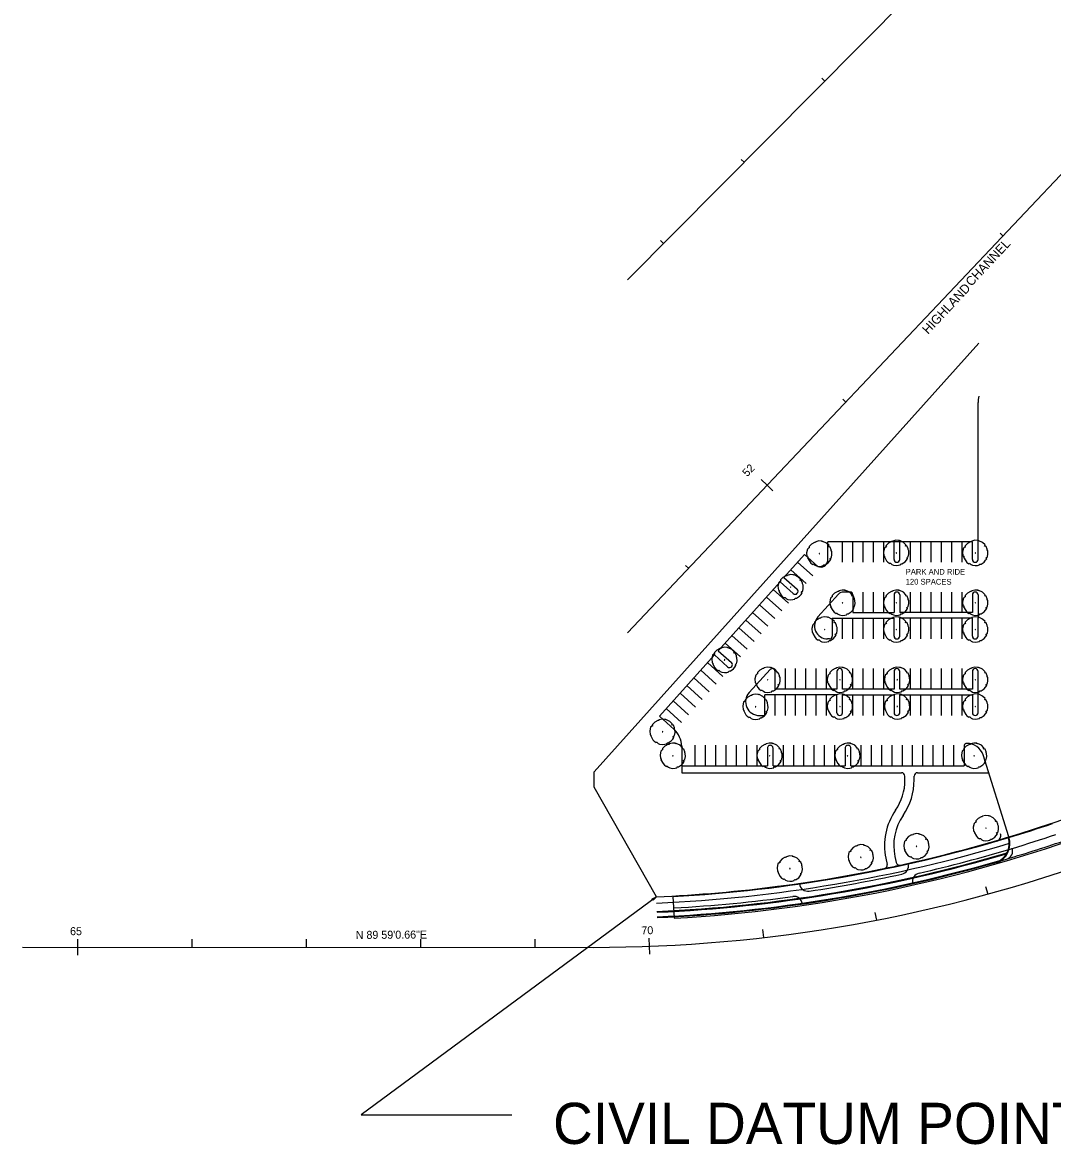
# Model space of a CAD drawing. Extents: x 6711323 to 6714641, y 1869258 to 1871224.
# Drawn here: x 6711323 to 6712223, y 1869258 to 1870239 of the extents above; entities that cross this region are included whole.
import ezdxf

# ---------------------------------------------------------------- set-up
doc = ezdxf.new("R2010")
doc.units = 0
for name, color, linetype in [('Level 10', 7, 'Continuous'), ('Level 11', 7, 'Continuous'), ('Level 13', 7, 'Continuous'), ('Level 14', 7, 'Continuous'), ('Level 15', 7, 'Continuous'), ('Level 16', 7, 'Continuous'), ('Level 18', 7, 'Continuous'), ('Level 2', 7, 'Continuous'), ('Level 3', 7, 'Continuous'), ('Level 32', 7, 'Continuous'), ('Level 35', 7, 'Continuous'), ('Level 46', 7, 'Continuous'), ('Level 63', 7, 'Continuous')]:
    doc.layers.add(name, color=color, linetype=linetype)

# ---------------------------------------------------------------- blocks, each defined once
blk = doc.blocks.new('TREE_1')
at = {"layer": 'Level 18'}
for p, q in [((-0.223, 0.51), (-0.357, 0.436)), ((-0.203, 0.506), (-0.223, 0.51)), ((-0.178, 0.51), (-0.203, 0.506)), ((-0.168, 0.532), (-0.178, 0.51)), ((-0.027, 0.572), (-0.168, 0.532)), ((0.117, 0.559), (-0.027, 0.572)), ((0.117, 0.537), (0.117, 0.559)), ((0.144, 0.55), (0.117, 0.537)), ((0.312, 0.471), (0.144, 0.55)), ((-0.539, 0.216), (-0.577, 0.053)), ((-0.577, 0.053), (-0.559, -0.123)), ((-0.491, 0.26), (-0.539, 0.216)), ((-0.46, 0.264), (-0.491, 0.26)), ((-0.46, 0.33), (-0.467, 0.29)), ((-0.467, 0.29), (-0.45, 0.286)), ((-0.357, 0.436), (-0.46, 0.33)), ((-0.45, 0.286), (-0.46, 0.264)), ((-0.003, 0.018), (-0.021, 0.009)), ((-0.021, 0.009), (-0.014, 0)), ((-0.014, 0), (0, 0)), ((0, 0), (-0.003, 0.018)), ((0.419, 0.365), (0.312, 0.471)), ((0.398, 0.317), (0.415, 0.334)), ((0.408, 0.308), (0.398, 0.317)), ((0.436, 0.317), (0.408, 0.308)), ((0.415, 0.334), (0.419, 0.365)), ((0.474, 0.295), (0.436, 0.317)), ((0.518, 0.185), (0.474, 0.295)), ((0.518, 0.15), (0.518, 0.185)), ((0.542, 0.101), (0.518, 0.15)), ((0.549, -0.031), (0.542, 0.101)), ((-0.559, -0.123), (-0.529, -0.136)), ((-0.525, -0.163), (-0.535, -0.176)), ((-0.535, -0.176), (-0.439, -0.343)), ((-0.529, -0.136), (-0.525, -0.163)), ((-0.439, -0.343), (-0.384, -0.414)), ((-0.384, -0.414), (-0.295, -0.466)), ((-0.295, -0.466), (-0.281, -0.458)), ((-0.281, -0.458), (-0.261, -0.449)), ((-0.261, -0.449), (-0.247, -0.466)), ((-0.247, -0.466), (-0.199, -0.506)), ((0.178, -0.506), (0.192, -0.488)), ((0.192, -0.488), (0.227, -0.484)), ((0.227, -0.484), (0.244, -0.488)), ((0.244, -0.488), (0.381, -0.396)), ((0.381, -0.396), (0.446, -0.317)), ((0.446, -0.317), (0.494, -0.246)), ((0.463, -0.207), (0.484, -0.189)), ((0.47, -0.229), (0.463, -0.207)), ((0.484, -0.229), (0.47, -0.229)), ((0.484, -0.189), (0.525, -0.163)), ((0.494, -0.246), (0.484, -0.229)), ((0.525, -0.163), (0.549, -0.031)), ((-0.199, -0.506), (-0.137, -0.537)), ((-0.137, -0.537), (-0.017, -0.554)), ((-0.017, -0.554), (0.089, -0.546)), ((0.089, -0.546), (0.175, -0.524)), ((0.175, -0.524), (0.178, -0.506))]:
    blk.add_line(p, q, dxfattribs=at)

msp = doc.modelspace()

# ---------------------------------------------------------------- linework, layer by layer
at = {"layer": 'Level 10'}
for radius, end in [(1262.51, 286.74398), (1269.84, 286.54272), (1270.51, 286.51109), (1274.53, 286.18152), (1275.2, 285.96183)]:
    msp.add_arc((6711821.84, 1870730.35), radius, 272.50226, end, dxfattribs=at)
at = {"layer": 'Level 11'}
for p, q in [((6712023.87, 1870187.68), (6712021.39, 1870190.15)), ((6711953.42, 1870116.72), (6711950.93, 1870119.19)), ((6711882.96, 1870045.76), (6711880.48, 1870048.22)), ((6711891.19, 1869474.76), (6711892.24, 1869455.79))]:
    msp.add_line(p, q, dxfattribs=at)
for centre, radius, start, end in [((6711821.85, 1870730.35), 1257.5, 286.77978, 288.60239), ((6711821.85, 1870730.35), 1257.5, 273.16115, 286.77978), ((6711821.85, 1870730.35), 1276.5, 273.16115, 290.14901), ((6712172.81, 1869528.03), 5, 286.27284, 17.69104), ((6711821.85, 1870730.35), 1267.5, 286.78697, 288.5952), ((6711821.85, 1870730.35), 1267.5, 282.97403, 286.78697), ((6711821.85, 1870730.35), 1275, 286.44789, 288.93429), ((6712180.73, 1869514.72), 7.5, 286.44789, 17.69109), ((6711821.85, 1870730.35), 1275, 273.16115, 286.44789), ((6712089.63, 1869501.69), 7.5, 282.29527, 12.63699), ((6712009.27, 1869486.89), 7.5, 188.22963, 278.57135), ((6711821.85, 1870730.35), 1265, 278.57135, 282.29527), ((6712108.1, 1869487.9), 7.5, 102.97403, 192.63699), ((6711821.85, 1870730.35), 1267.5, 273.16115, 277.89259), ((6711996.93, 1869467.43), 7.5, 8.22963, 97.89259)]:
    msp.add_arc(centre, radius, start, end, dxfattribs=at)
at = {"layer": 'Level 13'}
for p, q in [((6711851.4, 1869705.32), (6712288.61, 1870167.5)), ((6711322.58, 1869430.49), (6711821.47, 1869430.35))]:
    msp.add_line(p, q, dxfattribs=at)
msp.add_arc((6711821.85, 1870730.35), 1300, 269.98352, 290.14901, dxfattribs=at)
at = {"layer": 'Level 14'}
for p, q in [((6712179.7, 1870052.36), (6712177.15, 1870054.77)), ((6712042.25, 1869907.07), (6712039.71, 1869909.48)), ((6711968.45, 1869839.24), (6711973.53, 1869834.43)), ((6711973.53, 1869834.43), (6711978.62, 1869829.61)), ((6711904.81, 1869761.78), (6711902.27, 1869764.19))]:
    msp.add_line(p, q, dxfattribs=at)
for points in [[(6712164.55, 1869483.59), (6712166.4, 1869476.84)], [(6712067.73, 1869460.94), (6712069.06, 1869454.07)], [(6711370.57, 1869437.48), (6711370.57, 1869423.48)], [(6711470.57, 1869437.45), (6711470.57, 1869430.45)], [(6711570.57, 1869437.42), (6711570.57, 1869430.42)], [(6711670.57, 1869437.39), (6711670.57, 1869430.39)], [(6711770.57, 1869437.36), (6711770.57, 1869430.36)], [(6711870.3, 1869438.26), (6711870.82, 1869424.27)], [(6711969.45, 1869445.8), (6711970.25, 1869438.85)]]:
    msp.add_lwpolyline(points, dxfattribs=at)
at = {"layer": 'Level 15'}
msp.add_line((6711851.4, 1870013.97), (6713052.94, 1871224.17), dxfattribs=at)
at = {"layer": 'Level 3'}
for p, q in [((6711822.41, 1869583.72), (6712158.49, 1869958.67)), ((6711822.24, 1869570.35), (6711822.41, 1869583.72)), ((6711876.72, 1869474.55), (6711822.24, 1869570.35))]:
    msp.add_line(p, q, dxfattribs=at)
for centre, radius, start, end in [((6711821.84, 1870730.35), 1257, 284.61423, 290.14921), ((6711822.85, 1870726.48), 1253, 277.46109, 284.61423), ((6711821.84, 1870730.35), 1257, 272.50217, 277.46109)]:
    msp.add_arc(centre, radius, start, end, dxfattribs=at)
at = {"layer": 'Level 32'}
for p, q in [((6712157.99, 1869851.97), (6712157.99, 1869906.6)), ((6712157.99, 1869785.01), (6712157.99, 1869851.97)), ((6712026.51, 1869768.28), (6712026.51, 1869785.01)), ((6712152.99, 1869785.01), (6712026.51, 1869785.01)), ((6712039.49, 1869767.01), (6712039.49, 1869785.01)), ((6712048.49, 1869767.01), (6712048.49, 1869785.01)), ((6712057.49, 1869767.01), (6712057.49, 1869785.01)), ((6712066.49, 1869767.01), (6712066.49, 1869785.01)), ((6712075.49, 1869767.01), (6712075.49, 1869785.01)), ((6712084.49, 1869769.51), (6712084.49, 1869785.01)), ((6712089.49, 1869769.51), (6712089.49, 1869785.01)), ((6712098.99, 1869767.01), (6712098.99, 1869785.01)), ((6712107.99, 1869767.01), (6712107.99, 1869785.01)), ((6712116.99, 1869767.01), (6712116.99, 1869785.01)), ((6712125.99, 1869767.01), (6712125.99, 1869785.01)), ((6712134.99, 1869767.01), (6712134.99, 1869785.01)), ((6712143.99, 1869767.01), (6712143.99, 1869785.01)), ((6712152.99, 1869769.51), (6712152.99, 1869785.01)), ((6712157.99, 1869769.51), (6712157.99, 1869785.01)), ((6711988.23, 1869753.74), (6712006.26, 1869773.85)), ((6712006.26, 1869773.85), (6712017.98, 1869763.33)), ((6712000.25, 1869767.15), (6712013.65, 1869755.13)), ((6711988.23, 1869753.74), (6711999.78, 1869743.4)), ((6711994.24, 1869760.44), (6712007.65, 1869748.43)), ((6711930.83, 1869689.7), (6711984.9, 1869750.02)), ((6711978.89, 1869743.32), (6711992.29, 1869731.3)), ((6711996.44, 1869739.67), (6711984.9, 1869750.02)), ((6712046, 1869741.01), (6712040.39, 1869741.01)), ((6712057.49, 1869723.01), (6712057.49, 1869741.01)), ((6712066.49, 1869723.01), (6712066.49, 1869741.01)), ((6712075.49, 1869723.01), (6712075.49, 1869741.01)), ((6712098.99, 1869723.01), (6712098.99, 1869741.01)), ((6712107.99, 1869723.01), (6712107.99, 1869741.01)), ((6712116.99, 1869723.01), (6712116.99, 1869741.01)), ((6712125.99, 1869723.01), (6712125.99, 1869741.01)), ((6712134.99, 1869723.01), (6712134.99, 1869741.01)), ((6712143.99, 1869723.01), (6712143.99, 1869741.01)), ((6711972.88, 1869736.61), (6711986.29, 1869724.6)), ((6712035.95, 1869739.04), (6712017.97, 1869719.24)), ((6712048.5, 1869738.51), (6712048.5, 1869723.01)), ((6712084.49, 1869738.51), (6712084.49, 1869723.01)), ((6712089.49, 1869738.51), (6712089.49, 1869723.01)), ((6712152.99, 1869738.51), (6712152.99, 1869723.01)), ((6712157.99, 1869738.51), (6712157.99, 1869718.01)), ((6711960.87, 1869723.21), (6711974.27, 1869711.2)), ((6711966.88, 1869729.91), (6711980.28, 1869717.9)), ((6712048.5, 1869723.01), (6712084.49, 1869723.01)), ((6712152.99, 1869723.01), (6712089.49, 1869723.01)), ((6711954.86, 1869716.51), (6711968.27, 1869704.49)), ((6712030.5, 1869718.01), (6712030.5, 1869702.51)), ((6712030.5, 1869718.01), (6712084.49, 1869718.01)), ((6712039.49, 1869700.01), (6712039.49, 1869718.01)), ((6712048.49, 1869700.01), (6712048.49, 1869718.01)), ((6712057.49, 1869700.01), (6712057.49, 1869718.01)), ((6712066.49, 1869700.01), (6712066.49, 1869718.01)), ((6712075.49, 1869700.01), (6712075.49, 1869718.01)), ((6712084.49, 1869702.51), (6712084.49, 1869718.01)), ((6712152.99, 1869718.01), (6712089.49, 1869718.01)), ((6712089.49, 1869702.51), (6712089.49, 1869718.01)), ((6712098.99, 1869700.01), (6712098.99, 1869718.01)), ((6712107.99, 1869700.01), (6712107.99, 1869718.01)), ((6712116.99, 1869700.01), (6712116.99, 1869718.01)), ((6712125.99, 1869700.01), (6712125.99, 1869718.01)), ((6712134.99, 1869700.01), (6712134.99, 1869718.01)), ((6712143.99, 1869700.01), (6712143.99, 1869718.01)), ((6712152.99, 1869702.51), (6712152.99, 1869718.01)), ((6712157.99, 1869702.51), (6712157.99, 1869718.01)), ((6711942.85, 1869703.1), (6711956.25, 1869691.09)), ((6711948.85, 1869709.81), (6711962.26, 1869697.79)), ((6711936.84, 1869696.4), (6711950.24, 1869684.39)), ((6712028, 1869700.01), (6712026.48, 1869700.01)), ((6711879.44, 1869632.36), (6711927.5, 1869685.98)), ((6711939.04, 1869675.63), (6711927.5, 1869685.98)), ((6711930.83, 1869689.7), (6711942.38, 1869679.36)), ((6711915.48, 1869672.57), (6711928.89, 1869660.56)), ((6711921.49, 1869679.28), (6711934.89, 1869667.26)), ((6711976.15, 1869673.19), (6711957.89, 1869653.08)), ((6711989.5, 1869656.01), (6711989.5, 1869674.01)), ((6711998.5, 1869656.01), (6711998.5, 1869674.01)), ((6712007.5, 1869656.01), (6712007.5, 1869674.01)), ((6712016.5, 1869656.01), (6712016.5, 1869674.01)), ((6712025.5, 1869656.01), (6712025.5, 1869674.01)), ((6712048.49, 1869656.01), (6712048.49, 1869674.01)), ((6712057.49, 1869656.01), (6712057.49, 1869674.01)), ((6712066.49, 1869656.01), (6712066.49, 1869674.01)), ((6712075.49, 1869656.01), (6712075.49, 1869674.01)), ((6712098.99, 1869656.01), (6712098.99, 1869674.01)), ((6712107.99, 1869656.01), (6712107.99, 1869674.01)), ((6712116.99, 1869656.01), (6712116.99, 1869674.01)), ((6712125.99, 1869656.01), (6712125.99, 1869674.01)), ((6712134.99, 1869656.01), (6712134.99, 1869674.01)), ((6712143.99, 1869656.01), (6712143.99, 1869674.01)), ((6711909.47, 1869665.87), (6711922.88, 1869653.86)), ((6711980.5, 1869656.01), (6711980.5, 1869671.51)), ((6712034.5, 1869671.51), (6712034.5, 1869656.01)), ((6712039.5, 1869656.01), (6712039.5, 1869671.51)), ((6712084.49, 1869671.51), (6712084.49, 1869656.01)), ((6712089.49, 1869656.01), (6712089.49, 1869671.51)), ((6712152.99, 1869671.51), (6712152.99, 1869656.01)), ((6712157.99, 1869651.01), (6712157.99, 1869671.51)), ((6711903.47, 1869659.17), (6711916.87, 1869647.16)), ((6712034.5, 1869656.01), (6711980.5, 1869656.01)), ((6712084.49, 1869656.01), (6712039.5, 1869656.01)), ((6712152.99, 1869656.01), (6712089.49, 1869656.01)), ((6711891.45, 1869645.77), (6711904.86, 1869633.75)), ((6711897.46, 1869652.47), (6711910.86, 1869640.45)), ((6711971.5, 1869633.01), (6711971.5, 1869651.01)), ((6711980.5, 1869633.01), (6711980.5, 1869651.01)), ((6711989.5, 1869633.01), (6711989.5, 1869651.01)), ((6711998.5, 1869633.01), (6711998.5, 1869651.01)), ((6712007.5, 1869633.01), (6712007.5, 1869651.01)), ((6712016.5, 1869633.01), (6712016.5, 1869651.01)), ((6712025.5, 1869633.01), (6712025.5, 1869651.01)), ((6712034.5, 1869635.51), (6712034.5, 1869651.01)), ((6712039.5, 1869635.51), (6712039.5, 1869651.01)), ((6712039.5, 1869651.01), (6712084.49, 1869651.01)), ((6712048.49, 1869633.01), (6712048.49, 1869651.01)), ((6712057.49, 1869633.01), (6712057.49, 1869651.01)), ((6712066.49, 1869633.01), (6712066.49, 1869651.01)), ((6712075.49, 1869633.01), (6712075.49, 1869651.01)), ((6712084.49, 1869651.01), (6712084.49, 1869635.51)), ((6712089.49, 1869635.51), (6712089.49, 1869651.01)), ((6712089.49, 1869651.01), (6712152.99, 1869651.01)), ((6712098.99, 1869633.01), (6712098.99, 1869651.01)), ((6712107.99, 1869633.01), (6712107.99, 1869651.01)), ((6712116.99, 1869633.01), (6712116.99, 1869651.01)), ((6712125.99, 1869633.01), (6712125.99, 1869651.01)), ((6712134.99, 1869633.01), (6712134.99, 1869651.01)), ((6712143.99, 1869633.01), (6712143.99, 1869651.01)), ((6712152.99, 1869651.01), (6712152.99, 1869635.51)), ((6712157.99, 1869635.51), (6712157.99, 1869651.01)), ((6711885.45, 1869639.06), (6711898.85, 1869627.05)), ((6711966.77, 1869633.01), (6711971.5, 1869633.01)), ((6711892.21, 1869620.92), (6711879.44, 1869632.36)), ((6711898.86, 1869606.16), (6711898.97, 1869589.01)), ((6711910.77, 1869589.01), (6711910.77, 1869607.01)), ((6711919.77, 1869589.01), (6711919.77, 1869607.01)), ((6711928.77, 1869589.01), (6711928.77, 1869607.01)), ((6711937.77, 1869589.01), (6711937.77, 1869607.01)), ((6711946.77, 1869589.01), (6711946.77, 1869607.01)), ((6711955.77, 1869589.01), (6711955.77, 1869607.01)), ((6711964.77, 1869589.01), (6711964.77, 1869607.01)), ((6711973.77, 1869604.51), (6711973.77, 1869589.01)), ((6711978.77, 1869589.01), (6711978.77, 1869604.51)), ((6711987.77, 1869589.01), (6711987.77, 1869607.01)), ((6711996.77, 1869589.01), (6711996.77, 1869607.01)), ((6712005.77, 1869589.01), (6712005.77, 1869607.01)), ((6712014.77, 1869589.01), (6712014.77, 1869607.01)), ((6712023.77, 1869589.01), (6712023.77, 1869607.01)), ((6712032.77, 1869589.01), (6712032.77, 1869607.01)), ((6712041.77, 1869604.51), (6712041.77, 1869589.01)), ((6712046.77, 1869589.01), (6712046.77, 1869604.51)), ((6712055.77, 1869589.01), (6712055.77, 1869607.01)), ((6712064.77, 1869589.01), (6712064.77, 1869607.01)), ((6712073.77, 1869589.01), (6712073.77, 1869607.01)), ((6712082.77, 1869589.01), (6712082.77, 1869607.01)), ((6712091.77, 1869589.01), (6712091.77, 1869607.01)), ((6712100.77, 1869589.01), (6712100.77, 1869607.01)), ((6712109.77, 1869589.01), (6712109.77, 1869607.01)), ((6712118.77, 1869589.01), (6712118.77, 1869607.01)), ((6712127.77, 1869589.01), (6712127.77, 1869607.01)), ((6712136.77, 1869589.01), (6712136.77, 1869607.01)), ((6712184.78, 1869526.88), (6712162.37, 1869598.56)), ((6711898.97, 1869589.01), (6711899.01, 1869583.01)), ((6711978.77, 1869589.01), (6712041.77, 1869589.01)), ((6712046.77, 1869589.01), (6712145.77, 1869589.01)), ((6711899.01, 1869583.01), (6712091.01, 1869583.01)), ((6712094.05, 1869576.7), (6712094.03, 1869580.03)), ((6712102.05, 1869576.75), (6712102.03, 1869579.99)), ((6712105.01, 1869583.01), (6712167.24, 1869583.01)), ((6712077.4, 1869508.19), (6712078.52, 1869502.91)), ((6712085.23, 1869509.85), (6712086.35, 1869504.57))]:
    msp.add_line(p, q, dxfattribs=at)
for points in [[(6712034.5, 1869651.01), (6711971.5, 1869651.01)], [(6712145.77, 1869606.95), (6712145.77, 1869589.01)], [(6711899.01, 1869589.01), (6711973.77, 1869589.01)]]:
    msp.add_lwpolyline(points, dxfattribs=at)
for centre, radius, start, end in [((6712182.99, 1869906.6), 25, 167.0423, 180), ((6712020.41, 1869768.97), 6.13, 246.66575, 353.61228), ((6712086.99, 1869769.51), 2.5, 180, 0), ((6712155.49, 1869769.51), 2.5, 180, 0), ((6711998.11, 1869741.53), 2.5, 228.12933, 48.12933), ((6712040.39, 1869735.01), 6, 90, 137.75958), ((6712046, 1869738.51), 2.5, 0, 90), ((6712086.99, 1869738.51), 2.5, 0, 180), ((6712155.49, 1869738.51), 2.5, 0, 180), ((6712026.48, 1869711.51), 11.5, 137.75958, 270), ((6712028, 1869702.51), 2.5, 269.99417, 0), ((6712086.99, 1869702.51), 2.5, 180, 0), ((6712155.49, 1869702.51), 2.5, 180, 0), ((6711940.71, 1869677.49), 2.5, 228.12933, 48.12933), ((6711978, 1869671.51), 2.5, 0, 137.75958), ((6712037, 1869671.51), 2.5, 0, 180), ((6712086.99, 1869671.51), 2.5, 0, 180), ((6712155.49, 1869671.51), 2.5, 0, 180), ((6711966.77, 1869645.01), 12, 137.75958, 270), ((6712037, 1869635.51), 2.5, 180, 0), ((6712086.99, 1869635.51), 2.5, 180, 0), ((6712155.49, 1869635.51), 2.5, 180, 0), ((6711878.86, 1869606.03), 20, 0.36975, 48.12933), ((6711976.27, 1869604.51), 2.5, 359.99841, 180.00062), ((6712044.27, 1869604.51), 2.5, 359.99841, 180.00062), ((6712148.13, 1869606.12), 2.5, 89.63074, 160.46301), ((6712148.21, 1869593.62), 15, 19.24106, 90.36975), ((6712048.05, 1869576.4), 46, 325.25563, 0.36975), ((6712091.03, 1869580.01), 3, 0.36975, 90.36975), ((6712048.05, 1869576.4), 54, 325.25563, 0.36975), ((6712105.03, 1869580.01), 3, 90.36975, 180.36975), ((6712130.22, 1869519.41), 54, 145.25563, 191.99408), ((6712130.22, 1869519.41), 46, 145.25563, 191.99408), ((6712167.79, 1869520.95), 18, 289.34174, 19.24106), ((6712075.59, 1869502.29), 3, 281.67425, 11.99408), ((6711821.84, 1870730.35), 1257, 281.67425, 282.31392), ((6712089.28, 1869505.2), 3, 191.99408, 282.31391)]:
    msp.add_arc(centre, radius, start, end, dxfattribs=at)
at = {"layer": 'Level 35'}
msp.add_arc((6712167.79, 1869520.95), 17.5, 289.34174, 17.60382, dxfattribs=at)
at = {"layer": 'Level 46'}
for radius, end in [(1262.51, 286.74398), (1269.84, 286.54272), (1270.51, 286.51109), (1274.53, 286.18152), (1275.2, 285.96183)]:
    msp.add_arc((6711821.84, 1870730.35), radius, 272.50226, end, dxfattribs=at)
at = {"layer": 'Level 63'}
msp.add_lwpolyline([(6711876.72, 1869474.55), (6711618.74, 1869283.82), (6711750.34, 1869283.82)], dxfattribs=at)
msp.add_lwpolyline([(6711873.11, 1869472.71), (6711876.72, 1869474.55), (6711873.9, 1869471.63)], close=True, dxfattribs=at)

# ---------------------------------------------------------------- block references
at = {"layer": 'Level 18', "xscale": 19.68503819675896, "yscale": 19.685039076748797}
for p in [(6712019.42, 1869774.36), (6712086.64, 1869775.11), (6712155.79, 1869774.96), (6711994.4, 1869745.1), (6712039.62, 1869731.49), (6712086.64, 1869731.49), (6712155.79, 1869731.49), (6712024.07, 1869708.11), (6712086.64, 1869708.11), (6712155.79, 1869708.11), (6711936.54, 1869681.51), (6711974.2, 1869664.14), (6712037.48, 1869664.14), (6712087.47, 1869664.14), (6712155.79, 1869664.14), (6711963.64, 1869640.5), (6712037.48, 1869640.77), (6712087.47, 1869640.77), (6712155.79, 1869640.77), (6711882.31, 1869618.65), (6711891.29, 1869597.73), (6711976, 1869597.73), (6712044.02, 1869597.73), (6712154.72, 1869597.73), (6712165.1, 1869534.43), (6712104.3, 1869518.54), (6712055.68, 1869508.93), (6711993.67, 1869499.04)]:
    msp.add_blockref('TREE_1', p, dxfattribs=at)

# ---------------------------------------------------------------- texts
at = {"layer": 'Level 14'}
for s, rotation, p in [('65', 359.98352, (6711364.21, 1869440.98)), ('70', 2.14746, (6711863.76, 1869441.51)), ('N 89 59\'0.66"E', 0.3651, (6711613.95, 1869437.67))]:
    msp.add_text(s, height=7, rotation=rotation, dxfattribs=at).set_placement(p)
at = {"layer": 'Level 16'}
msp.add_text('52', height=7, rotation=45.20583, dxfattribs=at).set_placement((6711956.03, 1869841.32))
at = {"layer": 'Level 2'}
for s, height, rotation, p in [('CHANNEL', 8, 46.90961, (6712152.02, 1870007.68)), ('CHANNEL', 8, 46.90961, (6712152.02, 1870007.68)), ('HIGHLAND', 8, 46.90961, (6712114.24, 1869965.88)), ('HIGHLAND', 8, 46.90961, (6712114.24, 1869965.88)), ('PARK AND RIDE', 5, 359.88307, (6712094.66, 1869756.24)), ('120 SPACES', 5, 359.88307, (6712094.66, 1869747.52))]:
    msp.add_text(s, height=height, rotation=rotation, dxfattribs=at).set_placement(p)
at = {"layer": 'Level 63'}
msp.add_text('CIVIL DATUM POINT', height=36, dxfattribs=at).set_placement((6711786.43, 1869258.43))

doc.saveas('drawing.dxf')
